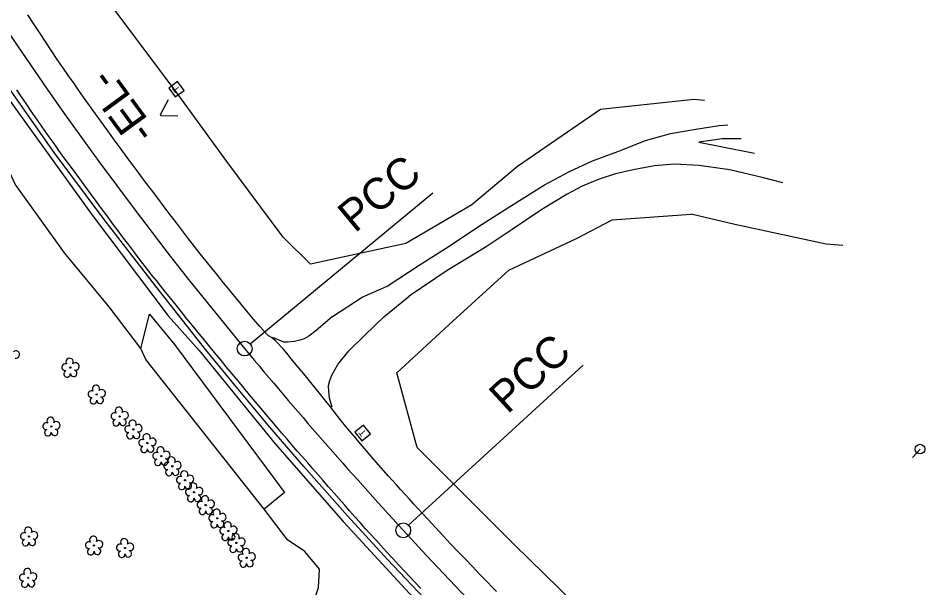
# Model space of a CAD drawing. Extents: x 477009 to 479892, y 492858 to 496862.
# Drawn here: x 478753.8 to 479213.4, y 494052.3 to 494341.3 of the extents above; entities that cross this region are included whole.
import ezdxf

# ---------------------------------------------------------------- set-up
doc = ezdxf.new("R2010")
doc.units = 0
for name, color, linetype in [('Exist Guardrail', 7, 'Continuous'), ('Exist Horizontal Alignment', 7, 'Continuous'), ('Exist Horizontal Alignment Direction Label', 7, 'Continuous'), ('Exist Other Culture Fence Line', 7, 'Continuous'), ('Exist Other Culture Sign', 7, 'Continuous'), ('Exist Roads EOP', 7, 'Continuous'), ('Exist Roads Soil', 7, 'Continuous'), ('Exist Utilities Power Pole CELL', 7, 'Continuous'), ('Exist Utilities Telephone Pedestal CELL', 7, 'Continuous'), ('Exist Vegetation Hedge Row', 7, 'Continuous'), ('Exist Vegetation Tree CELL', 7, 'Continuous'), ('Exist Vegetation Woods Line', 7, 'Continuous')]:
    doc.layers.add(name, color=color, linetype=linetype)

msp = doc.modelspace()

# ---------------------------------------------------------------- linework, layer by layer
at = {"layer": 'Exist Guardrail'}
for points in [[(478848.96, 494173.09), (478823.38, 494205.51), (478797.42, 494239.12), (478772.09, 494273.2), (478749.01, 494305.94), (478733.03, 494329.58), (478715.27, 494357.24), (478689.75, 494398.3), (478671.1, 494429.57), (478654.66, 494457.42), (478638.8, 494486.1), (478625.46, 494510.7), (478608.27, 494543.89), (478591.97, 494576.68), (478579.13, 494602.21), (478568.8, 494623)], [(479030.35, 493970.18), (479012.92, 493989.95), (478987.43, 494017.59), (478962.55, 494044.08), (478941.05, 494066.79), (478920.73, 494088.95), (478898.6, 494113.95), (478881.42, 494133.89), (478865.31, 494153.16), (478848.96, 494173.09)]]:
    msp.add_lwpolyline(points, dxfattribs=at)
at = {"layer": 'Exist Horizontal Alignment'}
for p, q in [((478871.47, 494176.12), (478963.91, 494252.69)), ((478951.74, 494084.09), (479040.17, 494165.25))]:
    msp.add_line(p, q, dxfattribs=at)
for centre in [(478868.59, 494173.72), (478948.97, 494081.55)]:
    msp.add_circle(centre, 3.75, dxfattribs=at)
for centre, radius, start, end in [((480407.9, 495448.91), 1998.89, 192.1328, 219.63873), ((480724.65, 495711.31), 2410.21, 219.63873, 222.54643), ((480415.92, 495427.95), 1991.17, 222.54643, 230.46528)]:
    msp.add_arc(centre, radius, start, end, dxfattribs=at)
at = {"layer": 'Exist Other Culture Fence Line'}
for points in [[(479002.57, 494213.48), (479036.8, 494229.61), (479054.99, 494239.08), (479094.91, 494241.92)], [(479171.86, 494225.96), (479163.46, 494226.73), (479117.11, 494236.72), (479094.91, 494241.92)], [(479108.16, 494017.94), (479070.79, 494024.96), (479052.06, 494028.2), (479035.55, 494044.67), (479005.51, 494074.07), (478956.05, 494123.48), (478945.66, 494161.44), (478974.21, 494187.61), (479002.57, 494213.48)]]:
    msp.add_lwpolyline(points, dxfattribs=at)
at = {"layer": 'Exist Other Culture Sign'}
for p, q in [((478826.01, 494292.37), (478829.91, 494299.97)), ((478826.4, 494291.68), (478826.01, 494292.37)), ((478834.78, 494291.56), (478826.4, 494291.68))]:
    msp.add_line(p, q, dxfattribs=at)
at = {"layer": 'Exist Roads EOP'}
for points in [[(478996.35, 494050.5), (478993.96, 494052.94), (478991.73, 494055.22), (478987.72, 494059.34), (478984.02, 494063.16), (478980.32, 494067.01), (478976.63, 494070.87), (478972.97, 494074.74), (478969.23, 494078.72), (478965.29, 494082.95), (478963.24, 494085.17), (478961.12, 494087.47), (478958.93, 494089.85), (478956.68, 494092.33), (478954.41, 494094.83), (478952.15, 494097.31), (478949.9, 494099.78), (478947.67, 494102.22), (478945.51, 494104.61), (478941.49, 494109.07), (478937.83, 494113.19), (478934.14, 494117.44), (478930.33, 494121.91), (478928.36, 494124.24), (478926.33, 494126.62), (478924.25, 494129.07), (478920.58, 494133.4), (478917.07, 494137.69), (478913.65, 494142.12), (478912.09, 494144.19), (478909.83, 494147.1), (478906.57, 494151.18), (478902.85, 494155.69), (478899.42, 494159.84), (478895.71, 494164.33), (478892.21, 494168.58), (478890.64, 494170.49), (478888.21, 494173.38), (478884.47, 494177.46), (478883.06, 494178.71), (478882.51, 494179.09), (478880.68, 494180.17), (478880.5, 494180.3), (478880.29, 494180.47), (478876.28, 494184.92), (478873.16, 494188.55), (478869.66, 494192.73), (478866.19, 494197.02), (478863.51, 494200.33), (478860.77, 494203.64), (478857.92, 494207.08), (478854.95, 494210.76), (478851.95, 494214.5), (478849, 494218.13), (478846.06, 494221.77), (478843.11, 494225.52), (478840.12, 494229.38), (478837.06, 494233.38), (478833.98, 494237.45), (478830.87, 494241.53), (478827.74, 494245.67), (478824.56, 494249.92), (478821.38, 494254.18), (478818.24, 494258.34), (478815.15, 494262.44), (478812.09, 494266.55), (478809.04, 494270.67), (478806.01, 494274.79), (478803, 494278.91), (478800, 494283.03), (478796.96, 494287.22), (478793.85, 494291.54), (478790.76, 494295.86), (478787.8, 494300.05), (478784.94, 494304.13), (478782.14, 494308.11), (478779.35, 494312.09), (478776.5, 494316.2), (478773.62, 494320.42), (478770.72, 494324.75), (478767.8, 494329.15), (478764.85, 494333.56), (478761.84, 494338.11), (478758.68, 494342.91)], [(478957.83, 494052.08), (478955.21, 494054.87), (478952.51, 494057.77), (478949.7, 494060.78), (478946.78, 494063.92), (478943.76, 494067.17), (478940.74, 494070.44), (478937.83, 494073.6), (478935.04, 494076.65), (478932.37, 494079.6), (478929.75, 494082.52), (478927.11, 494085.46), (478924.47, 494088.45), (478921.82, 494091.46), (478919.17, 494094.5), (478916.5, 494097.55), (478913.83, 494100.6), (478911.16, 494103.67), (478908.48, 494106.72), (478905.82, 494109.76), (478903.17, 494112.77), (478900.54, 494115.77), (478897.91, 494118.75), (478895.3, 494121.74), (478892.71, 494124.74), (478890.12, 494127.74), (478887.52, 494130.77), (478884.89, 494133.86), (478882.22, 494137.01), (478879.52, 494140.23), (478876.77, 494143.51), (478873.96, 494146.86), (478871.11, 494150.27), (478868.2, 494153.76), (478865.25, 494157.3), (478862.28, 494160.87), (478859.29, 494164.48), (478856.27, 494168.13), (478853.28, 494171.75), (478850.38, 494175.29), (478847.55, 494178.75), (478844.81, 494182.12), (478842.09, 494185.47), (478839.36, 494188.86), (478836.6, 494192.28), (478833.82, 494195.73), (478831.1, 494199.12), (478828.53, 494202.33), (478826.1, 494205.36), (478823.82, 494208.22), (478821.59, 494211.02), (478819.33, 494213.89), (478817.04, 494216.83), (478814.72, 494219.82), (478812.33, 494222.94), (478809.82, 494226.25), (478807.2, 494229.74), (478804.46, 494233.41), (478801.67, 494237.18), (478798.87, 494240.96), (478796.06, 494244.74), (478793.25, 494248.53), (478790.46, 494252.3), (478787.69, 494256.05), (478784.96, 494259.77), (478782.26, 494263.47), (478779.6, 494267.12), (478777, 494270.71), (478774.46, 494274.24), (478771.97, 494277.71), (478769.53, 494281.14), (478767.12, 494284.54), (478764.74, 494287.92), (478762.4, 494291.27), (478760.08, 494294.63), (478757.75, 494298.02), (478755.41, 494301.44), (478753.07, 494304.9)]]:
    msp.add_lwpolyline(points, dxfattribs=at)
at = {"layer": 'Exist Roads Soil'}
for points in [[(478913.17, 494189.91), (478928.2, 494199.78), (478940.82, 494205.45), (478957.08, 494216.02), (478972.25, 494225.73), (478987.15, 494235.58), (479002.07, 494245.1), (479020.64, 494256.78), (479033.32, 494263.58), (479044.95, 494268.91), (479057.78, 494273.59), (479071.85, 494279.19), (479084.54, 494282.82), (479097.39, 494284.99), (479109.19, 494286.94), (479113.54, 494287.13)], [(479120.23, 494280.09), (479110.63, 494280.04), (479098.89, 494278.4), (479109.97, 494276.29), (479127.06, 494272.9)], [(479141.5, 494257.7), (479131.65, 494260.33), (479114.52, 494264.34), (479098.78, 494266.55), (479086.52, 494267.2), (479076.43, 494266.45), (479065.58, 494264.37), (479056.56, 494262.29), (479048.38, 494259.65), (479039.73, 494256.05), (479032.15, 494252.06), (479019.33, 494244.25), (479004.28, 494234.18), (478990.95, 494225.27), (478971.24, 494213.28), (478952.06, 494200.3)], [(478912.92, 494143.96), (478911.68, 494148.52), (478911.21, 494152.15), (478911.11, 494154.94), (478911.74, 494157.59), (478912.71, 494160.28), (478915.75, 494165.6), (478921.38, 494172.54), (478929.59, 494180.44), (478939.21, 494189.87), (478948.21, 494197.2), (478952.06, 494200.3)], [(478913.17, 494189.91), (478904.64, 494182.77), (478901.11, 494180), (478898.7, 494178.7), (478896.6, 494177.91), (478893.82, 494177.33), (478890.38, 494177), (478888.53, 494176.99), (478882.89, 494179.35)]]:
    msp.add_lwpolyline(points, dxfattribs=at)
at = {"layer": 'Exist Utilities Power Pole CELL'}
for q in [(479207.19, 494118.55), (479210.99, 494122.71)]:
    msp.add_line((479210.99, 494122.71), q, dxfattribs=at)
msp.add_circle((479210.99, 494122.71), 2.45, dxfattribs=at)
at = {"layer": 'Exist Utilities Telephone Pedestal CELL'}
for p, q in [((478834.04, 494305.16), (478834.04, 494305.16)), ((478928.47, 494130.82), (478928.47, 494130.82))]:
    msp.add_line(p, q, dxfattribs=at)
for points in [[(478837.93, 494304.63), (478834.63, 494309.14), (478830.11, 494305.84), (478833.41, 494301.33), (478837.93, 494304.63)], [(478932.38, 494130.53), (478928.81, 494134.83), (478924.5, 494131.26), (478928.08, 494126.95), (478932.38, 494130.53)]]:
    msp.add_lwpolyline(points, dxfattribs=at)
at = {"layer": 'Exist Vegetation Hedge Row'}
for points in [[(478815.93, 494173.7), (478799.98, 494194.82), (478777.28, 494222.27), (478752.25, 494257.11), (478745.05, 494272.95), (478737.95, 494282.98), (478724.96, 494297.54), (478708.38, 494326.9), (478687.37, 494360.79)], [(478713.16, 494353.28), (478739.04, 494313.7), (478791.02, 494241.9), (478829.88, 494190.36), (478845.51, 494172.66)], [(478845.51, 494172.66), (478883.99, 494125.4), (478918.58, 494086.08), (478977.87, 494021.65), (478972.39, 494009.31), (478959.23, 494006.7), (478935.26, 494009.43), (478912.01, 494018.49), (478896.29, 494022.75), (478906.04, 494052.55), (478906.48, 494061.88), (478899.05, 494070.85), (478890.35, 494076.64), (478878.48, 494092.19)]]:
    msp.add_lwpolyline(points, dxfattribs=at)
at = {"layer": 'Exist Vegetation Tree CELL'}
for p, q in [((478780.25, 494164.07), (478780.25, 494164.07)), ((478793.63, 494150.44), (478793.63, 494150.44)), ((478805.19, 494139.28), (478805.19, 494139.28)), ((478770.57, 494134.17), (478770.57, 494134.17)), ((478812.17, 494132.7), (478812.17, 494132.7)), ((478819.28, 494125.77), (478819.28, 494125.77)), ((478826.33, 494119.15), (478826.33, 494119.15)), ((478831.92, 494114.01), (478831.92, 494114.01)), ((478838.37, 494106.94), (478838.37, 494106.94)), ((478842.95, 494100.82), (478842.95, 494100.82)), ((478848.89, 494094.35), (478848.89, 494094.35)), ((478854.75, 494087.61), (478854.75, 494087.61)), ((478759.26, 494078.4), (478759.26, 494078.4)), ((478860.36, 494081.19), (478860.36, 494081.19)), ((478792.26, 494073.85), (478792.26, 494073.85)), ((478864.42, 494075.15), (478864.42, 494075.15)), ((478807.94, 494072.57), (478807.94, 494072.57)), ((478869.61, 494067.64), (478869.61, 494067.64)), ((478758.84, 494057.44), (478758.84, 494057.44))]:
    msp.add_line(p, q, dxfattribs=at)
for centre in [(478780.25, 494164.07), (478793.63, 494150.44), (478805.19, 494139.28), (478770.57, 494134.17), (478812.17, 494132.7), (478819.28, 494125.77), (478826.33, 494119.15), (478831.92, 494114.01), (478838.37, 494106.94), (478842.95, 494100.82), (478848.89, 494094.35), (478854.75, 494087.61), (478759.26, 494078.4), (478860.36, 494081.19), (478792.26, 494073.85), (478864.42, 494075.15), (478807.94, 494072.57), (478869.61, 494067.64), (478758.84, 494057.44)]:
    msp.add_circle(centre, 0.326, dxfattribs=at)
for centre, radius, start, end in [((478752.61, 494170.75), 1.9, 257.1011, 134.1999), ((478777.64, 494164.23), 1.73, 62.6636, 279.3457), ((478779.86, 494166.95), 1.86, 330.1651, 219.7134), ((478782.8, 494164.66), 1.9, 257.1011, 134.1999), ((478778.55, 494160.95), 1.69, 111.5671, 6.231), ((478781.92, 494161.17), 1.7, 181.2822, 74.56), ((478791.02, 494150.6), 1.73, 62.6636, 279.3457), ((478793.24, 494153.32), 1.86, 330.1651, 219.7134), ((478796.18, 494151.03), 1.9, 257.1011, 134.1999), ((478791.92, 494147.32), 1.69, 111.5671, 6.231), ((478795.3, 494147.54), 1.7, 181.2822, 74.56), ((478804.81, 494142.15), 1.86, 330.1651, 219.7134), ((478770.19, 494137.05), 1.86, 330.1651, 219.7134), ((478802.59, 494139.43), 1.73, 62.6636, 279.3457), ((478806.86, 494136.38), 1.7, 181.2822, 74.56), ((478807.74, 494139.87), 1.9, 257.1011, 134.1999), ((478767.97, 494134.33), 1.73, 62.6636, 279.3457), ((478773.12, 494134.76), 1.9, 257.1011, 134.1999), ((478803.49, 494136.16), 1.69, 111.5671, 6.231), ((478809.56, 494132.86), 1.73, 62.6636, 279.3457), ((478811.78, 494135.58), 1.86, 330.1651, 219.7134), ((478814.72, 494133.29), 1.9, 257.1011, 134.1999), ((478768.87, 494131.05), 1.69, 111.5671, 6.231), ((478772.25, 494131.27), 1.7, 181.2822, 74.56), ((478810.46, 494129.58), 1.69, 111.5671, 6.231), ((478813.84, 494129.8), 1.7, 181.2822, 74.56), ((478818.9, 494128.65), 1.86, 330.1651, 219.7134), ((478816.67, 494125.93), 1.73, 62.6636, 279.3457), ((478817.58, 494122.65), 1.69, 111.5671, 6.231), ((478820.95, 494122.87), 1.7, 181.2822, 74.56), ((478821.83, 494126.36), 1.9, 257.1011, 134.1999), ((478823.72, 494119.3), 1.73, 62.6636, 279.3457), ((478825.94, 494122.02), 1.86, 330.1651, 219.7134), ((478828.88, 494119.74), 1.9, 257.1011, 134.1999), ((478824.63, 494116.03), 1.69, 111.5671, 6.231), ((478828, 494116.25), 1.7, 181.2822, 74.56), ((478829.32, 494114.16), 1.73, 62.6636, 279.3457), ((478831.54, 494116.88), 1.86, 330.1651, 219.7134), ((478834.47, 494114.6), 1.9, 257.1011, 134.1999), ((478830.22, 494110.89), 1.69, 111.5671, 6.231), ((478833.6, 494111.11), 1.7, 181.2822, 74.56), ((478837.98, 494109.81), 1.86, 330.1651, 219.7134), ((478835.76, 494107.09), 1.73, 62.6636, 279.3457), ((478840.04, 494104.04), 1.7, 181.2822, 74.56), ((478840.91, 494107.53), 1.9, 257.1011, 134.1999), ((478836.66, 494103.82), 1.69, 111.5671, 6.231), ((478840.35, 494100.98), 1.73, 62.6636, 279.3457), ((478842.57, 494103.7), 1.86, 330.1651, 219.7134), ((478845.5, 494101.41), 1.9, 257.1011, 134.1999), ((478841.25, 494097.7), 1.69, 111.5671, 6.231), ((478844.63, 494097.92), 1.7, 181.2822, 74.56), ((478848.5, 494097.22), 1.86, 330.1651, 219.7134), ((478851.44, 494094.94), 1.9, 257.1011, 134.1999), ((478846.28, 494094.5), 1.73, 62.6636, 279.3457), ((478847.18, 494091.23), 1.69, 111.5671, 6.231), ((478850.56, 494091.45), 1.7, 181.2822, 74.56), ((478854.37, 494090.48), 1.86, 330.1651, 219.7134), ((478852.15, 494087.76), 1.73, 62.6636, 279.3457), ((478857.3, 494088.19), 1.9, 257.1011, 134.1999), ((478758.88, 494081.27), 1.86, 330.1651, 219.7134), ((478853.05, 494084.48), 1.69, 111.5671, 6.231), ((478856.42, 494084.71), 1.7, 181.2822, 74.56), ((478857.75, 494081.34), 1.73, 62.6636, 279.3457), ((478859.97, 494084.06), 1.86, 330.1651, 219.7134), ((478862.91, 494081.78), 1.9, 257.1011, 134.1999), ((478756.66, 494078.55), 1.73, 62.6636, 279.3457), ((478761.81, 494078.99), 1.9, 257.1011, 134.1999), ((478791.88, 494076.72), 1.86, 330.1651, 219.7134), ((478858.65, 494078.07), 1.69, 111.5671, 6.231), ((478862.03, 494078.29), 1.7, 181.2822, 74.56), ((478864.03, 494078.03), 1.86, 330.1651, 219.7134), ((478757.56, 494075.28), 1.69, 111.5671, 6.231), ((478760.94, 494075.5), 1.7, 181.2822, 74.56), ((478789.66, 494074), 1.73, 62.6636, 279.3457), ((478794.81, 494074.44), 1.9, 257.1011, 134.1999), ((478805.34, 494072.73), 1.73, 62.6636, 279.3457), ((478807.56, 494075.45), 1.86, 330.1651, 219.7134), ((478810.49, 494073.16), 1.9, 257.1011, 134.1999), ((478861.81, 494075.31), 1.73, 62.6636, 279.3457), ((478862.71, 494072.03), 1.69, 111.5671, 6.231), ((478866.09, 494072.25), 1.7, 181.2822, 74.56), ((478866.97, 494075.74), 1.9, 257.1011, 134.1999), ((478790.56, 494070.73), 1.69, 111.5671, 6.231), ((478793.94, 494070.95), 1.7, 181.2822, 74.56), ((478806.24, 494069.45), 1.69, 111.5671, 6.231), ((478809.62, 494069.68), 1.7, 181.2822, 74.56), ((478867.01, 494067.79), 1.73, 62.6636, 279.3457), ((478869.23, 494070.51), 1.86, 330.1651, 219.7134), ((478872.16, 494068.22), 1.9, 257.1011, 134.1999), ((478867.91, 494064.51), 1.69, 111.5671, 6.231), ((478871.29, 494064.74), 1.7, 181.2822, 74.56), ((478758.45, 494060.31), 1.86, 330.1651, 219.7134), ((478761.39, 494058.03), 1.9, 257.1011, 134.1999), ((478756.23, 494057.59), 1.73, 62.6636, 279.3457), ((478757.13, 494054.32), 1.69, 111.5671, 6.231), ((478760.51, 494054.54), 1.7, 181.2822, 74.56)]:
    msp.add_arc(centre, radius, start, end, dxfattribs=at)
at = {"layer": 'Exist Vegetation Woods Line'}
for points in [[(479101.8, 494299.48), (479096.32, 494300.1), (479049.04, 494294.92), (479006.84, 494266.09), (478983.81, 494246.55), (478950.37, 494226.98), (478901.94, 494216.55), (478888.04, 494230.14), (478859.58, 494268.63), (478835.28, 494302.1), (478794.29, 494356.87), (478755.58, 494402.83), (478730.62, 494444.98), (478696.86, 494491.29), (478678.12, 494505.61), (478645.77, 494567.98), (478614.57, 494622.64), (478600.77, 494655.77)], [(478818.51, 494168.16), (478815.93, 494173.7), (478820.35, 494191.25), (478833, 494175.84)], [(478833, 494175.84), (478888.78, 494100.67), (478878.48, 494092.19)], [(478878.48, 494092.19), (478818.51, 494168.16)]]:
    msp.add_lwpolyline(points, dxfattribs=at)

# ---------------------------------------------------------------- texts
at = {"layer": 'Exist Horizontal Alignment'}
for rotation, p in [(39.6387, (478924.43, 494231.97)), (42.5464, (479001.83, 494140.11))]:
    msp.add_text('PCC', height=16, rotation=rotation, dxfattribs=at).set_placement(p)
at = {"layer": 'Exist Horizontal Alignment Direction Label'}
msp.add_text('-EL-', height=16, rotation=126.237, dxfattribs=at).set_placement((478824.13, 494284.13))
at = {"layer": 'Exist Utilities Telephone Pedestal CELL'}
for rotation, p in [(126.1636, (478836.09, 494305.26)), (129.6796, (478930.51, 494131.04))]:
    msp.add_text('T', height=3.42, rotation=rotation, dxfattribs=at).set_placement(p)

doc.saveas('drawing.dxf')
